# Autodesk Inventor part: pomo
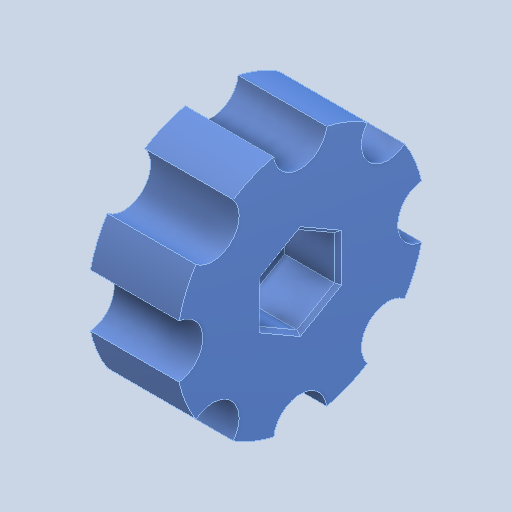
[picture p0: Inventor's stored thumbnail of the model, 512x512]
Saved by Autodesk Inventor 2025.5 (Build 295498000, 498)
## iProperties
Created: 2026-10
Part Number: pomo
Material: Genérico
Document SubType Name: Modeling
Designer: Luis M
Density: 1 g/cm^3
Appearance: Valor por defecto
Author: Luis M
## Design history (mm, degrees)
feature "Base1"
node "Sólido1"
